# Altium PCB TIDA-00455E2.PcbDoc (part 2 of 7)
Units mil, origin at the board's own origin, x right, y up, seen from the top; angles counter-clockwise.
Board outline 6693 x 6693.1 mil, 8 copper layers (Layer 1 - Top Layer, Layer 2 - GND, Layer 3 - Sensitive, Layer 4 - GND, Layer 5 - PWR, Layer 6 - Signal, Layer 7 - GND, Layer 8 - Bottom Layer), stack 63.122 mil thick; 537 components, 407 nets, 1686 pads, 1249 vias.
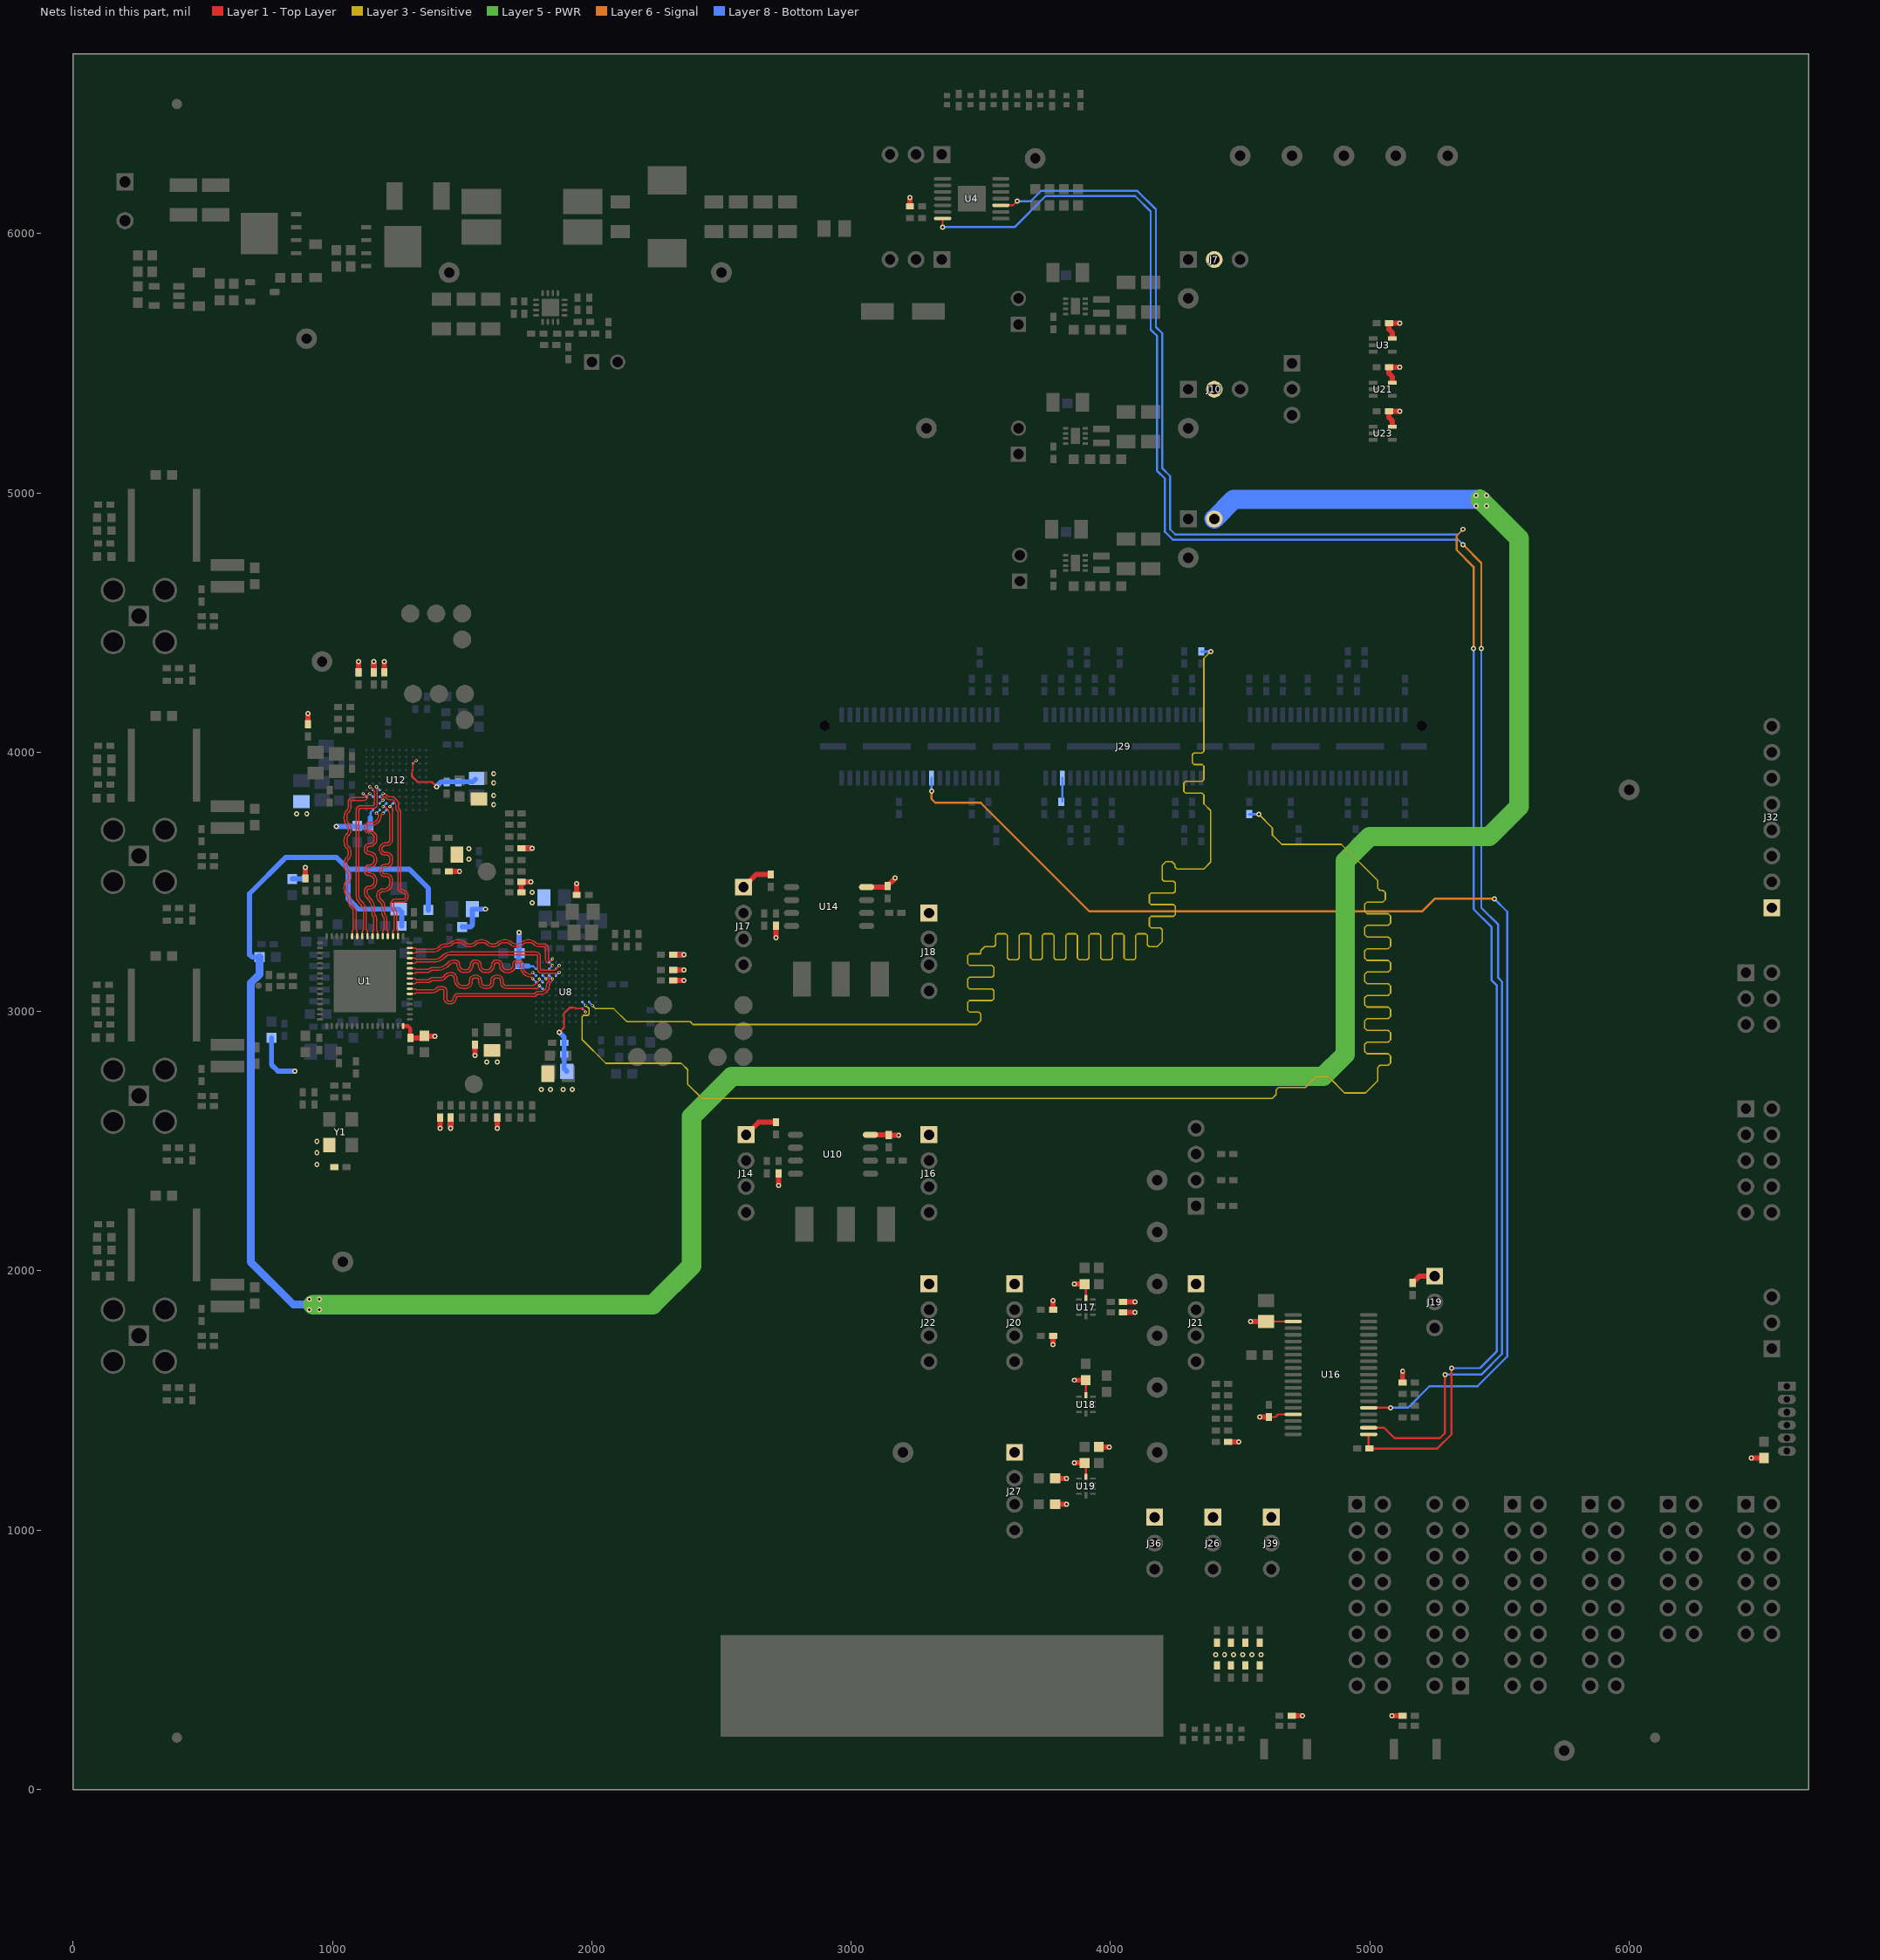
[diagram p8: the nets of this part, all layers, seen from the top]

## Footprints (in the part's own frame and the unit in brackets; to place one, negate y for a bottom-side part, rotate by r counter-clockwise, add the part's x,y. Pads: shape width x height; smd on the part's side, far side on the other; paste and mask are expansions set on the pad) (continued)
Samtec_QTE-060-01-x-D-A [mm] "Header, 0.8mm, 60x2, SMT"
  rect 0.46x1.45 smd: 1(-27.595,3.09) 2(-27.595,-3.08) 3(-26.795,3.09) 4(-26.795,-3.08) 5(-25.995,3.09) 6(-25.995,-3.08) 7(-25.195,3.09) 8(-25.195,-3.08) 9(-24.395,3.09) 10(-24.395,-3.08) 11(-23.595,3.09) 12(-23.595,-3.08) 13(-22.795,3.09) 14(-22.795,-3.08) 15(-21.995,3.09) 16(-21.995,-3.08) 17(-21.195,3.09) 18(-21.195,-3.08) 19(-20.395,3.09) 20(-20.395,-3.08) 21(-19.595,3.09) 22(-19.595,-3.08) 23(-18.795,3.09) 24(-18.795,-3.08) 25(-17.995,3.09) 26(-17.995,-3.08) 27(-17.195,3.09) 28(-17.195,-3.08) 29(-16.395,3.09) 30(-16.395,-3.08) 31(-15.595,3.09) 32(-15.595,-3.08) 33(-14.795,3.09) 34(-14.795,-3.08) 35(-13.995,3.09) 36(-13.995,-3.08) 37(-13.195,3.09) 38(-13.195,-3.08) 39(-12.395,3.09) 40(-12.395,-3.08) 41(-7.595,3.09) 42(-7.595,-3.08) 43(-6.795,3.09) 44(-6.795,-3.08) 45(-5.995,3.09) 46(-5.995,-3.08) 47(-5.195,3.09) 48(-5.195,-3.08) 49(-4.395,3.09) 50(-4.395,-3.08) 51(-3.595,3.09) 52(-3.595,-3.08) 53(-2.795,3.09) 54(-2.795,-3.08) 55(-1.995,3.09) 56(-1.995,-3.08) 57(-1.195,3.09) 58(-1.195,-3.08) 59(-0.395,3.09) 60(-0.395,-3.08) 61(0.405,3.09) 62(0.405,-3.08) 63(1.205,3.09) 64(1.205,-3.08) 65(2.005,3.09) 66(2.005,-3.08) 67(2.805,3.09) 68(2.805,-3.08) 69(3.605,3.09) 70(3.605,-3.08) 71(4.405,3.09) 72(4.405,-3.08) 73(5.205,3.09) 74(5.205,-3.08) 75(6.005,3.09) 76(6.005,-3.08) 77(6.805,3.09) 78(6.805,-3.08) 79(7.605,3.09) 80(7.605,-3.08) 81(12.405,3.09) 82(12.405,-3.08) 83(13.205,3.09) 84(13.205,-3.08) 85(14.005,3.09) 86(14.005,-3.08) 87(14.805,3.09) 88(14.805,-3.08) 89(15.605,3.09) 90(15.605,-3.08) 91(16.405,3.09) 92(16.405,-3.08) 93(17.205,3.09) 94(17.205,-3.08) 95(18.005,3.09) 96(18.005,-3.08) 97(18.805,3.09) 98(18.805,-3.08) 99(19.605,3.09) 100(19.605,-3.08) 101(20.405,3.09) 102(20.405,-3.08) 103(21.205,3.09) 104(21.205,-3.08) 105(22.005,3.09) 106(22.005,-3.08) 107(22.805,3.09) 108(22.805,-3.08) 109(23.605,3.09) 110(23.605,-3.08) 111(24.405,3.09) 112(24.405,-3.08) 113(25.205,3.09) 114(25.205,-3.08) 115(26.005,3.09) 116(26.005,-3.08) 117(26.805,3.09) 118(26.805,-3.08) 119(27.605,3.09) 120(27.605,-3.08)
  round 1.02 hole 1.02 unplated mask+0: MH1(-29.24,2.04) MH2(29.24,2.04)
  rect 2.54x0.64 smd: MP1(-28.445,0) MP4(-11.555,0) MP5(-8.445,0) MP8(8.445,0) MP9(11.555,0) MP12(28.445,0)
  rect 4.7x0.64 smd: MP2(-23.175,0) MP3(-16.825,0) MP6(-3.175,0) MP7(3.175,0) MP10(16.825,0) MP11(23.175,0)
  silkscreen extent -30,-2.98 30.01,3.25, body extent -30,-3.56 30.01,3.56, height 4.34
SM_RADIAL_D [mm] "6.3 x 5.8mm:  Panasonic D"
  rect 3.2x1.6 smd: 1(-2.5,0) 2(2.5,0)
  silkscreen extent -3.4,-3.4 3.4,3.4, body extent -3.41,-3.41 3.41,3.41, height 6.1
SMC [mil] "Molded Diode, 2-Leads, Body 6.9x5.8mm, IPC Medium Density, based on OnSemi component dimensions and land patterns"
  rect 110x150 smd: 1(-140.49,0) 2(140.49,0)
  silkscreen extent -221,-124 189,123, body extent -156,-116 156,116, height 91
SML-P1_GREEN [mm] "ROHM"
  rect 0.5x0.6 smd: 1(-0.45,0) 2(0.45,0)
  silkscreen extent -0.95,-0.3 -0.95,0.3, body extent -0.53,-0.33 0.53,0.33, height 0.25
SML-P1_RED [mm] "ROHM"
  rect 0.5x0.6 smd: 1(-0.45,0) 2(0.45,0)
  silkscreen extent -0.95,-0.3 -0.95,0.3, body extent -0.52,-0.33 0.52,0.33, height 0.25
SML-P1_YELLOW-GREEN [mm] "Rohm Semiconductor"
  rect 0.5x0.6 smd: 1(-0.45,0) 2(0.45,0)
  silkscreen extent -0.63,-0.61 1.33,0.61, body extent -0.55,-0.35 0.55,0.35, height 0.25
SOD-123 [mm] "On Semi recommended land pattern"
  rect 0.915x1.22 smd: 1(-1.637,0) 2(1.637,0)
  silkscreen extent -2.74,-1.17 2.03,1.17, body extent -1.93,-0.9 1.93,0.9, height 1.35
SOIC127P800X216-8N [mm] "SOIC, 8-Leads, Body 5.3x5.3mm (max), Pitch 1.27mm, IPC Medium Density"
  oval 1.5x0.6 smd: 1(-3.675,1.905) 2(-3.675,0.635) 3(-3.675,-0.635) 4(-3.675,-1.905) 5(3.675,-1.905) 6(3.675,-0.635) 7(3.675,0.635) 8(3.675,1.905)
  silkscreen extent -4.11,-2.7 2.69,2.7, body extent -4.1,-2.7 4.1,2.7, height 2.17
SOT-23 [mm] "SOT23, 3-Leads, Body 2.9x1.3mm, Pitch 0.95mm, Lead Span 2.5mm, IPC Medium Density"
  rrect50% 1x0.6 smd: 1(-1.2,0.95) 2(-1.2,-0.95) 3(1.2,0)
  silkscreen extent -1.63,-1.5 0.7,1.5, body extent -1.16,-1.45 1.21,1.45, height 1
SW_SKRKAEE010 [mm] "Alps recommended land pattern"
  rect 0.8x2 smd: 1(-2.1,0) 2(2.1,0)
  body extent -2.4,-1.45 2.4,1.45, height 1.96
Testpoint_Keystone_Miniature [mil] "Miniature SMT test point"
  rect 135x70 smd: 1(0,0)
  silkscreen extent -78,-46 78,45, body extent -52,-20 52,20, height 61
TI_Stacked_SolderMask_Medium [mil]
  rect 1706x392 smd paste-196 mask-196: 0(0,0)
TP_25MIL-SMT [mil]
  round 25 smd mask-2.5: 1(0,0)
TSW-102-07-G-S [mm] "Samtec 100mil, 1x2, 230 mil above insulator"
  rect 1.65x1.65 hole 1.016 mask+0: 1(-1.27,0)
  round 1.65 hole 1.016 mask+0: 2(1.27,0)
  silkscreen extent -3.56,-1.27 2.54,1.27, body extent -2.54,-1.27 2.54,1.27, height 8.38
TSW-103-07-G-D [mm] "Samtec 100mil, 2x3, 230 mil above insulator"
  rect 1.65x1.65 hole 1.016: 1(-2.54,-1.27)
  round 1.65 hole 1.016: 2(-2.54,1.27) 3(0,-1.27) 4(0,1.27) 5(2.54,-1.27) 6(2.54,1.27)
  silkscreen extent -4.83,-2.54 3.81,2.54, body extent -3.81,-2.54 3.81,2.54, height 8.38
TSW-103-07-G-S [mm] "Samtec 100mil, 1x3, 230 mil above insulator"
  rect 1.65x1.65 hole 1.016: 1(-2.54,0)
  round 1.65 hole 1.016: 2(0,0) 3(2.54,0)
  silkscreen extent -4.84,-1.27 3.81,1.27, body extent -3.81,-1.27 3.81,1.27, height 8.38
TSW-104-07-G-S [mm] "Samtec 100mil, 1x4, 230 mil above insulator"
  rect 1.65x1.65 hole 1.016 mask+0: 1(-3.81,0)
  round 1.65 hole 1.016 mask+0: 2(-1.27,0) 3(1.27,0) 4(3.81,0)
  silkscreen extent -6.1,-1.27 5.08,1.27, body extent -5.08,-1.27 5.08,1.27, height 8.38
TSW-105-07-G-D [mm] "Samtec 100mil, 2x5, 230 mil above insulator"
  rect 1.65x1.65 hole 1.016 mask+0: 1(-5.08,-1.27)
  round 1.65 hole 1.016 mask+0: 2(-5.08,1.27) 3(-2.54,-1.27) 4(-2.54,1.27) 5(0,-1.27) 6(0,1.27) 7(2.54,-1.27) 8(2.54,1.27) 9(5.08,-1.27) 10(5.08,1.27)
  silkscreen extent -7.37,-2.54 6.35,2.54, body extent -6.35,-2.54 6.35,2.54, height 8.38
TSW-106-07-G-D [mm] "Samtec 100mil, 2x6, 230 mil above insulator"
  rect 1.65x1.65 hole 1.016 mask+0: 1(-6.35,-1.27)
  round 1.65 hole 1.016 mask+0: 2(-6.35,1.27) 3(-3.81,-1.27) 4(-3.81,1.27) 5(-1.27,-1.27) 6(-1.27,1.27) 7(1.27,-1.27) 8(1.27,1.27) 9(3.81,-1.27) 10(3.81,1.27) 11(6.35,-1.27) 12(6.35,1.27)
  silkscreen extent -8.64,-2.54 7.62,2.54, body extent -7.62,-2.54 7.62,2.54, height 8.38
TSW-108-07-G-D [mm] "Samtec 100mil, 2x8, 230 mil above insulator"
  rect 1.65x1.65 hole 1.016 mask+0: 1(-8.89,-1.27)
  round 1.65 hole 1.016 mask+0: 2(-8.89,1.27) 3(-6.35,-1.27) 4(-6.35,1.27) 5(-3.81,-1.27) 6(-3.81,1.27) 7(-1.27,-1.27) 8(-1.27,1.27) 9(1.27,-1.27) 10(1.27,1.27) 11(3.81,-1.27) 12(3.81,1.27) 13(6.35,-1.27) 14(6.35,1.27) 15(8.89,-1.27) 16(8.89,1.27)
  silkscreen extent -11.18,-2.54 10.16,2.54, body extent -10.16,-2.54 10.16,2.54, height 8.38
TSW-108-07-G-S [mm] "Samtec 100mil, 1x8, 230 mil above insulator"
  rect 1.65x1.65 hole 1.016 mask+0: 1(-8.89,0)
  round 1.65 hole 1.016 mask+0: 2(-6.35,0) 3(-3.81,0) 4(-1.27,0) 5(1.27,0) 6(3.81,0) 7(6.35,0) 8(8.89,0)
  silkscreen extent -11.18,-1.27 10.16,1.27, body extent -10.16,-1.27 10.16,1.27, height 8.38
TXC_7C [mm] "TXC"
  rect 1.2x1.4 smd: 1(-1.1,1.27) 2(-1.1,-1.27) 3(1.1,-1.27) 4(1.1,1.27)
  silkscreen extent -2.32,-2.63 1.73,2.63, body extent -1.7,-2.6 1.7,2.6, height 1.4
VLS201610ET [mm] "TDK"
  rect 0.65x1.6 smd: 1(-0.675,0) 2(0.675,0)
  silkscreen extent -0.15,-1.02 0.15,1.02, body extent -1.05,-0.85 1.05,0.85, height 0.95
XTAL_ABM10 [mm] "ABRACON"
  rect 0.8x0.9 smd: 1(-0.625,0.825) 2(-0.625,-0.825) 3(0.625,-0.825) 4(0.625,0.825)
  silkscreen extent -1.28,-0.13 1.05,1.52, body extent -1.05,-1.3 1.05,1.3, height 0.7

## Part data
C1 C3 C5 C7 C15 C17 C19 C21 C115 C122 C124 C126 C127 C129 C130 C131 C135 C142 C144 C146 C147 C149 C150 C151 C160 C162: "CAP, CERM, 0.1 µF, 50 V, +/- 10%, X7R, 0402"
C2 C4 C6 C8 C16 C18 C20 C22: "CAP CER 4.7UF 25V 10% X5R 0603"
C9 C10 C23 C24 C78 C79: "CAP, CERM, 0.033 µF, 50 V, +/- 10%, X7R, 0402"
C11 C12 C25 C26: "CAP, CERM, 0.015 µF, 50 V, +/- 10%, X7R, 0402"
C13 C14 C27 C28: "CAP, CERM, 240 pF, 50 V, +/- 5%, C0G/NP0, 0402"
C29 C32: "CAP, CERM, 0.1uF, 50V, +10/%, X7R, 0603"
C30 C31: "Cap, Cer-X7R, 2.2uF, 100V, 10%, 1210"
C33 C34 C35 C36: "CAP, CERM, 4.7uF, 25V, +/-20%, X7R, 1206"
C37 C157: "Cap, Cer-X7R, 0.1uF, 6.3V, 10%, 0402"
C38 C39 C40: "Cap, Cer-X7R, 10uF, 25V, 10%, 1206"
C41: "Cap, Cer-X7R, 0.047uF, 6.3V, 10%, 0402"
C42: "Cap, Cer-X7R, 100pF, 50V, 10%, 0402"
C43: "Cap, Cer-X7R, 10000pF, 16V, 10%, 0402"
C44 C48 C51: "Cap, Cer-X7R, 10uF, 16V, 10%, 1206"
C45 C49 C52: "CAP, CERM, 22 µF, 16 V, +/- 10%, X5R, 1206"
C46 C50 C53: library part GRM31CR61C226KE15L, "CAP, open, 1206"
C47: "CAP, AL, 47 µF, 25 V, +/- 20%, 0.36 ohm, SMD"
C54 C60 C92: "CAP, CERM, 10 µF, 25 V, +/- 10%, X5R, 0805"
C56 C61 C69 C75 C94 C100 C106 C111 C163 C164: "CAP, CERM, 1 µF, 35 V, +/- 10%, JB, 0402"
C57 C62 C70 C76 C84 C90 C95 C101 C107 C112: library part GRM188R71C474KA88D, "CAP, CERM, 0.1uF, 50V, +/-10%, X7R, 0402"
C58 C63 C64 C65 C66 C71 C77 C85 C91 C96 C97 C102 C103 C108 C113 C114: "CAP, CERM, 0.01uF, 50V, +/-10%, C0G/NP0, 0402"
C72 C86: "CAP, CERM, 0.1uF, 50V, +/-20%, C0G/NP0, 0402"
C80 C155: library part Capacitor, "Cap, Cer-X7R, 2200pF, 50V, 10%, 0402"
C116 C119 C125 C136 C139 C145: "CAP, CERM, 10 µF, 6.3 V, +/- 20%, X7R, 0805"
C117 C137: "CAP, CERM, 2.2 µF, 10 V, +/- 20%, X5R, 0603"
C118 C120 C138 C140: "CAP, CERM, 0.47 µF, 10 V, +/- 10%, X5R, 0402"
C121 C141: "CAP, CERM, 4.7 µF, 10 V, +/- 10%, X5R, 0402"
C123 C143: "CAP, CERM, 2.2 µF, 10 V, +/- 10%, X5R, 0805"
C128 C134 C148 C154: "CAP, CERM, 18 pF, 100 V, +/- 5%, C0G/NP0, 0603"
C132 C133 C152 C153: "CAP, CERM, 1 µF, 16 V, +/- 10%, X5R, 0603"
C156: "Cap, Cer-X7R, 4.7uF, 10V, 10%, 0805"
C158 C159 C161: "CAP, CERM, 0.1uF, 16V, +/-5%, X7R, 0603"
D1 D2: "Diode, Zener, 15 V, 500 mW, SOD-123"
D3: "Diode, Schottky, 3A, 60V, SMC"
D4 D10: "LED, Yellow, SMD"
D5 D8: "LED, Orange, SMD"
D6: "LED, Red, SMD"
D7 D11 D12: "LED, Green, SMD"
D9: "LED, Yellow/green, SMD"
FID1 FID2 FID3 FID4 FID5 FID6: "Fiducial mark.  There is nothing to buy or mount."
J1 J2 J3 J4: "RIGHT ANGLE PLUG FOR PCB"
J5: "Conn Term Block, 2POS, 3.81mm, TH"
J6 J7 J8 J10 J11 J19 J26 J36 J39 J40: "Header, 100mil, 3x1, Gold, TH"
J9 J13 J15 J30: "Header, 100mil, 2x1, Tin, TH"
J12: "Header, 100mil, 2x1, Gold, TH"
J14 J16 J17 J18 J20 J21 J22 J24 J27: "Header, 100mil, 4x1, Gold, TH"
J23: "Receptacle, 50mil, 6x1, Gold, R/A, TH"
J25: "Header, 100mil, 5x2, Gold, TH"
J28 J33 J37 J38: "Header, 100mil, 8x2, Gold, TH"
J29: "Header, 0.8mm, 60x2, Gold, SMT"
J31: "Header, 100mil, 3x2, Gold, TH"
J32: "Header, 100mil, 8x1, Gold, TH"
J34 J35: "Header, 100mil, 6x2, Gold, TH"
L1 L2 L9 L10: "FERRITE CHIP 1000 OHM 400MA 0603"
L3 L5 L11 L13: "Inductor, Wirewound, Ferrite, 10 µH, 0.5 A, 0.57 ohm, SMD"
L4 L6 L12 L14: "Inductor, Shielded Drum Core, Ferrite, 100 µH, 0.7 A, 0.28 ohm, SMD"
L7 L8 L15 L16: "Ferrite Bead, 1000 ohm @ 100 MHz, 0.25 A, 0402"
L17: "Ind, Dual, 2.2uH, 20%, 6.23A, 8.05mE, Shielded, SMD"
L18 L19 L20: library part VLS201610ET-2R2M, "Inductor, Shielded, Ferrite, 2.2 µH, 1.45 A, 0.170 ohm, SMD"
L21: "Ferrite Bead, 120 ohm @ 100 MHz, 3 A, 0603"
L22 L23 L27 L28 L30: library part BLM18SG331TN1D, "1.5A Ferrite Bead, 330 ohm @ 100MHz, SMD"
L31 L32 L33 L34 L35 L36: "Ferrite Bead, 1000 ohm @ 100 MHz, 0.3 A, 0805"
Logo1: library part TI_Logo, "Texas Instrument Corporate Signature"
Logo2: library part Pb-Free
M1: "MOSFET, N/P-CH, 60 V, 4.4 A, SOT-23"
Q1 Q2: "MOSFET, P-CH, -60V, 30A, PowerPAK_SO-8L"
R1 R3 R9 R11: "RES, 2.00 k, 1%, 0.1 W, 0603"
R2 R4 R10 R12: "RES, 1.00 k, 1%, 0.1 W, 0603"
R5 R6 R13 R14: "RES, 57.6, 1%, 0.063 W, 0402"
R7 R8 R15 R16 R143 R145 R147: "RES, 200, 5%, 0.063 W, 0402"
R17: "RES, 0, 5%, 0.75 W, 2010"
R18 R22: library part Resistor, "Res, Chip, 100K, 1/10W, 1%, 0603"
R19 R20: "Res, Chip, 20K, 1/10W, 1%, 0603"
R21: library part CRCW060311R8FKEA, "RES, 11.8 ohm, 1%, 0.1W, 0603"
R23: "RES, 1.00k ohm, 1%, 0.1W, 0603"
R24 R136 R139: "Res, Chip, 0E, 1/8W, JUMP, 0805"
R25: "Res, Chip, 100K, 1/4W, 5%, 1206"
R26 R102 R104 R116 R119 R120 R141 R144 R146 R148 R149 R150: "Res, Chip, 10K, 1/16W, 5%, 0402"
R27: "RES, 2.32k ohm, 1%, 0.063W, 0402"
R28: "RES, 18.2k ohm, 1%, 0.063W, 0402"
R29: "RES, 49.9 ohm, 1%, 0.063W, 0402"
R30: "RES, 88.7 k, 1%, 0.063 W, 0402"
R31: "RES, 10.0k ohm, 1%, 0.063W, 0402"
R32 R33 R34 R35 R142 R156: "RES, 0 ohm, 5%, 0.1W, 0603"
R36 R38 R39 R41 R42 R44: "RES, 100 k, 1%, 0.1 W, 0603"
R37: "RES, 316 k, 1%, 0.1 W, 0603"
R40: "RES, 124 k, 1%, 0.1 W, 0603"
R43: "RES, 37.4 k, 1%, 0.1 W, 0603"
R45 R54: "RES, 10k ohm, 5%, 0.063W, 0402"
R46 R47 R62 R77 R80 R81 R92 R107 R110 R111: "RES, 0, 5%, 0.063 W, 0402"
R48: "RES, 13.3 k, 1%, 0.063 W, 0402"
R49: "RES, 40.2 k, 1%, 0.063 W, 0402"
R50 R64 R68 R94 R98 R125 R127: "RES, 2.2 k, 5%, 0.063 W, 0402"
R51 R159 R162: "RES, 100 ohm, 1%, 0.063W, 0402"
R52 R78 R108 R126 R128 R151 R152 R163 R164 R165 R166 R174 R175 R176 R177 R178 R179 R180 R181 R182 R186 R187 R188 R189 R190 R191 R192 R193 R194 R195 R196 R197 R198 R199 R200 R202 R203 R205 R206 R207 R208 R209 R210 R211 R212 R213 R214 R215 R216 R217 R218 R219 R220 R221 R222 R223 R224: "RES, 0 ohm, 5%, 0.063W, 0402"
R53: "RES, 56.2 k, 1%, 0.063 W, 0402"
R55: "RES, 210 k, 1%, 0.063 W, 0402"
R56 R57 R84 R85 R86 R87 R114 R115: "RES, 4.7 k, 5%, 0.063 W, 0402"
R58 R59 R60 R61 R63 R65 R66 R67 R72 R74 R75 R76 R82 R83 R88 R89 R90 R91 R93 R95 R96 R97 R105 R106 R112 R113 R129 R133 R134 R137 R138 R184 R185 R201 R204: "RES, 10 k, 5%, 0.063 W, 0402"
R69 R70 R71 R73 R99 R100 R101 R103: "RES, 33, 5%, 0.063 W, 0402"
R79 R109 R157 R158 R160 R161: "RES, 1.0 M, 5%, 0.063 W, 0402"
R117: "RES, 49.9 k, 1%, 0.063 W, 0402"
R118 R132: "RES, 220, 5%, 0.063 W, 0402"
R121 R122 R123 R124: "Res, Chip, 4.7K, 1/16W, 5%, 0402"
R130: "RES, 360, 5%, 0.063 W, 0402"
R131: "RES, 470, 5%, 0.063 W, 0402"
R135 R153 R167 R171 R172: "RES, 4.7k ohm, 5%, 0.1W, 0603"
R140 R155: "RES, 4.99 k, 1%, 0.063 W, 0402"
R154: "RES, 4.12 k, 1%, 0.063 W, 0402"
R168 R173: "RES, 487 ohm, 1%, 0.063W, 0402"
S1 S2: "Switch, Tactile, 12v, 50mA, Vertical, SMD"
TP1 TP2 TP3 TP4 TP5 TP6 TP7 TP9 TP10 TP12 TP14: "Test Point, Miniature, Red, TH"
TP8 TP11 TP13 TP15 TP43 TP44 TP45 TP46: "Test Point, Miniature, Black, TH"
TP16 TP17: "Test Point, O.025\""
TP18 TP19 TP20 TP21 TP22 TP23: "Test Point, Miniature, SMT"
TP24 TP25 TP26 TP27 TP28: "Test Point, Miniature, Yellow, TH"
TP29 TP30 TP31 TP32 TP33 TP34 TP35 TP36 TP37 TP38 TP39 TP40 TP41 TP42 TP47 TP48 TP49 TP50: library part PogoPad, "Pad for Pogo Pin Connector"
U1: "FPD-Link III Camera Hub Deserializer, RTD0064E"
U2: library part TLVH431AQDBVRQ1, "Automotive Catalog Low-Voltage Adjustable Precision Shunt Regulator, 80 mA, -40 to 125 degC, 5-pin SOT-23 (DBV), Green (RoHS & no Sb/Br)"
U3 U21 U23: "Single Bus Buffer Gate With 3-State Output, DCK0005A"
U4: "40V/100mO Single Channel Smart High Side Switch, Automotive Qualified, PWP0014C"
U5 U6 U7: "3-V to 17-V 1-A Step-Down Converter with DCS-Control™, DSG0008A"
U8 U12: "Companion ISP processor, BGA100"
U10 U14: "3V 128M-bit Serial Flash Memory With Dual SPI&QPI, SO-8"
U16: "16 MHz Mixed Signal Microcontroller with 32 KB Flash, 1024 B SARM and 32 GPIOs, -40 to 105 degC, 38-pin SOP (DA)"
U17: "IC, TS3USB221A-Q1, Dual USB Switch, UQFN-10"
U18 U19: "Automotive Catalog ESD Protected, High-Speed USB 2.0 (480-Mbps) 1:2 Multiplexer / Demultiplexer Switch, 16 ohm RON, 2.5 to 3.3V, -40 to 125 degC, 10-Pin UQFN (RSE), Green (RoHS & no Sb/Br)"
U20: "Integrated 5-A 40-V Wide Input Range Boost/SEPIC/Flyback DC-DC Regulator, RTE0016C"
Y1: "XO, 25.000MHz, 2.5V, SMD"
Y2 Y3: "Crystal, 24.576MHz, 10pF, SMD"
ZZ1 ZZ2 ZZ3: library part AssemblyNote

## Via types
v1: diameter 20, hole 10, Layer 1 - Top Layer to Layer 8 - Bottom Layer, tented both sides, 1063 vias
v2: diameter 12, hole 6, Layer 1 - Top Layer to Layer 8 - Bottom Layer, tented bottom, 140 vias
v3: diameter 19.68, hole 7.87, Layer 1 - Top Layer to Layer 8 - Bottom Layer, 38 vias
v4: diameter 19.68, hole 7.87, Layer 1 - Top Layer to Layer 8 - Bottom Layer, tented top, 4 vias
v5: diameter 15.75, hole 7.87, Layer 1 - Top Layer to Layer 8 - Bottom Layer, 4 vias

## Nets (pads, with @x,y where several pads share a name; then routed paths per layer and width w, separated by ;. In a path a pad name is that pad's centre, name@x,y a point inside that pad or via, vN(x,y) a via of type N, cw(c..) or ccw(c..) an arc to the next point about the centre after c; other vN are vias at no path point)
1V1: C92.1 J12.2 L27.1 L28.1 L30.1 | length 11569.3
  Layer 5 - PWR w75: 925,1870 2235,1870 2385,2020 2385,2595 2540,2750 4820,2750 4905,2835 4905,3580 5000,3675 5460,3675 5575,3790 5575,4825 v1(5450,4950) 5425,4975
  Layer 8 - Bottom Layer w20: L30.1@718.5,3210 690,3210 680,3220 680,3455 820,3595 1015,3595 1060.74,3549.26 ; L27.1@1266.5,3330 1266.5,3383.5 C92.1@1255,3395 1100,3395 1060.74,3434.26 1060.74,3549.26 ; L28.1@1370,3391.5 1370,3475 1295.74,3549.26 1060.74,3549.26
  Layer 8 - Bottom Layer w30: L30.1@718.5,3210 718.5,3143.5 685,3110 685,2035 850,1870 900,1870
  Layer 8 - Bottom Layer w75: J12.2@4400,4900 4475,4975 5425,4975 5440,4960
  other v1: 910,1850 950,1850 910,1890 950,1890 5410,4950 5410,4990 5450,4990
1V8: C54.1 C131.1 C132.2 C151.1 C152.2 J10.2 L21.1 L22.1 L23.1 L31.2 L34.2 R45.1 R48.2 R53.2 R136.1 R139.1 U8.K9 U12.K9 Y1.4 | length 885.2
  Layer 1 - Top Layer w20: R48.2@895,3513.62 v1(895,3555)
  Layer 8 - Bottom Layer w8: 1146.24,3747.5 1146.24,3766.91 U12.K9@1156.67,3777.34 ; 1755,3175 1774.41,3175 U8.K9@1784.84,3164.57
  Layer 8 - Bottom Layer w20: L22.1@765,2898.5 765,2795 790,2770 v1(855,2770) ; L23.1@845,3511.5 R53.2@892.87,3511.5 ; R53.2@895,3513.62 v1(895,3555) ; v1(1015,3714) C152.2@1096.24,3714 ; C152.2@1099.11,3711.12 1146.24,3711.12 1146.24,3747.5 ; L21.1@1500,3326.5 1531.5,3326.5 1540,3335 C54.1@1540,3395 v1(1590,3395) ; C132.2@1718.62,3222.13 C131.1@1718.62,3175 1755,3175 ; v1(1720,3305) 1720,3226.5 C132.2@1721.5,3225
  other v1: 940,2410 940,2455 940,2500 1805,2700 1840,2700 1770,3420 1770,3460 861.24,3762.5 901.24,3762.5 1621.24,3797.5 1621.24,3832.5
3V3: C75.1 C106.1 C107.1 C108.1 C125.1 C126.1 C127.2 C145.1 C146.1 C147.2 C156.1 C157.1 C158.1 C159.1 C161.1 C163.1 C164.1 J7.2 J14.1 J16.1 J17.1 J18.1 J19.1 J20.1 J21.1 J22.1 J26.1 J27.1 J32.1 J36.1 J39.1 L33.2 L36.2 R56.2 R57.2 R58.2 R59.2 R60.2 R61.1 R64.2 R65.2 R66.2 R67.2 R72.2 R74.2 R77.2 R78.1 R82.2 R83.2 R86.2 R87.2 R88.2 R89.2 R90.2 R91.1 R94.2 R95.2 R96.2 R97.2 R102.2 R104.2 R107.2 R108.1 R112.2 R113.2 R116.2 R119.2 R120.2 R121.2 R122.2 R123.2 R124.2 R141.2 R142.2 R144.2 R146.2 R148.2 R149.2 R150.2 R157.2 R160.2 R167.2 R171.2 R172.2 R184.2 U1.16 U3.5 U8.C3 U10.8 U12.C3 U14.8 U16.2 U16.16 U17.10 U18.10 U19.10 U21.5 U23.5 | length 4088.4
  Layer 1 - Top Layer w5: 1306.24,3917.5 1306.24,3927.5 1310.22,3931.48 1310.22,3956.48 v2(1323.01,3969.27) ; 1925,3015 1935,3015 1938.98,3011.02 1963.98,3011.02 v2(1976.77,2998.23)
  Layer 1 - Top Layer w8: 1306.24,3917.5 1306.24,3907.5 1328.24,3885.5 1383.24,3885.5 v1(1401.24,3867.5) ; v1(1875,2920) 1893,2938 1893,2993 1915,3015 1925,3015 ; C159.1@3900,1258.5 3905,1253.5 U19.10@3905,1205.43 ; C161.1@3900,1948.5 3905,1943.5 U17.10@3905,1895.43 ; U18.10@3905,1520.43 C158.1@3905,1578.5 ; C156.1@4600,1804.72 U16.2@4704.33,1804.72 ; C157.1@4610,1436.38 4636.38,1436.38 4646.46,1446.46 U16.16@4704.33,1446.46
  Layer 1 - Top Layer w15: U1.16@1276,2944.27 1290.73,2944.27 1300,2935 C108.1@1300,2898.62
  Layer 1 - Top Layer w20: R108.1@905,4108.62 v1(905,4150) ; R87.2@1100,4308.62 v1(1100,4350) ; R94.2@1160,4308.62 v1(1160,4350) ; R74.2@1200,4308.62 v1(1200,4350) ; C108.1@1300,2898.62 1347.13,2898.62 C107.1@1355,2906.5 1356.5,2905 v1(1395,2905) ; v1(1415,2550) R66.2@1415,2591.38 ; R107.2@1448.62,3540 v1(1490,3540) ; v1(1455,2550) R65.2@1455,2591.38 ; v1(1550,2831) R77.2@1550,2871.38 ; v1(1635,2550) R83.2@1635,2591.38 ; R96.2@1728.62,3460 R95.2@1728.62,3500 v1(1765,3500) ; R113.2@1728.62,3630 v1(1770,3630) ; R78.1@1941.38,3450 v1(1941.38,3493.62) ; R72.2@2313.62,3120 v1(2355,3120) ; R64.2@2313.62,3160 v1(2355,3160) ; R57.2@2313.62,3220 v1(2355,3220) ; J17.1@2585,3480 2633.62,3528.62 R89.2@2690,3528.62 ; J14.1@2595,2525 2643.62,2573.62 R59.2@2710,2573.62 ; v1(2710.51,3285) R90.2@2710.51,3331.38 ; v1(2720,2330) R60.2@2720,2376.38 ; U14.8@3059.69,3480 3136.38,3480 R91.1@3140,3483.62 3140,3485 v1(3170,3515) ; U10.8@3074.68,2525 R61.1@3143.62,2525 ; R61.1@3145,2525 R61.1@3143.62,2525 ; v1(3183.62,2523.62) R61.1@3145,2523.62 R61.1@3143.62,2525 ; R184.2@3226.38,6105 v1(3226.38,6138.62) ; v1(3778.62,1715) R122.2@3778.62,1750 ; R121.2@3778.62,1850 v1(3778.62,1885) ; R171.2@3786.5,1100 v1(3830,1100) ; R172.2@3786.5,1200 v1(3830,1200) ; v1(3860,1260) 3898.5,1260 C159.1@3900,1258.5 ; v1(3860,1578.5) C158.1@3905,1578.5 ; v1(3860,1950) 3898.5,1950 C161.1@3900,1948.5 ; R167.2@3955,1321.5 3956.5,1320 v1(3995,1320) ; R124.2@4048.62,1840 v1(4095,1840) ; R123.2@4048.62,1880 v1(4095,1880) ; R157.2@4453.62,1340 v1(4495,1340) ; v1(4540,1805) C156.1@4600,1805 ; v1(4575,1436.38) C157.1@4610,1436.38 ; R116.2@4698.62,285 v1(4740,285) ; v1(5085,285) R141.2@5126.38,285 ; U23.5@5087.4,5260 5087.4,5277.6 5073.62,5291.38 C164.1@5073.62,5315 v1(5115,5315) ; U21.5@5087.4,5430 5087.4,5447.6 5073.62,5461.38 C163.1@5073.62,5485 v1(5115,5485) ; U3.5@5087.4,5600 5087.4,5617.6 5073.62,5631.38 C75.1@5073.62,5655 v1(5115,5655) ; R160.2@5126.38,1570 v1(5126.38,1613.62) ; R102.2@5165,1953.62 5191.38,1980 J19.1@5250,1980 ; v1(6471.5,1278.5) R142.2@6520,1278.5
  Layer 8 - Bottom Layer w5: U12.C3@1310.22,3956.48 v2(1323.01,3969.27) ; U8.C3@1963.98,3011.02 v2(1976.77,2998.23)
  Layer 8 - Bottom Layer w20: R86.2@1100,4308.62 v1(1100,4350) ; R88.2@1160,4308.62 v1(1160,4350) ; C106.1@1300,2898.62 1342.13,2898.62 1348.5,2905 v1(1395,2905) ; v1(1401.24,3867.5) 1419.86,3886.12 1441.24,3886.12 1541.4,3886.12 C145.1@1551.24,3895.96 ; v1(1455,2550) R67.2@1455,2591.38 ; v1(1635,2550) R82.2@1635,2591.38 ; R97.2@1728.62,3500 v1(1765,3500) ; R112.2@1728.62,3630 v1(1770,3630) ; v1(1875,2920) 1893.62,2901.38 C126.1@1893.62,2880 C127.2@1893.62,2835 1893.62,2779.84 C125.1@1903.46,2770 ; R58.2@2313.62,3160 v1(2355,3160) ; R56.2@2313.62,3220 v1(2355,3220)
  other v1: 4405,520 4440,520 4475,520 4510,520 4545,520 4580,520 1890,2700 1925,2700 1595,2805 1635,2805 1526.24,3587.5 1526.24,3627.5 1621.24,3882.5 1621.24,3917.5
APP_BD_PORZ: J29.76 R214.1 | length 91.2
  Layer 8 - Bottom Layer w8: R214.1@3813.97,3809.66 J29.76@3813.97,3900.89
CAM_PW_CS: U4.14 U16.21 | length 7318.1
  Layer 1 - Top Layer w8: v1(3352.8,6025) U4.14@3352.8,6058.23 ; U16.21@4995.67,1395.28 5054.72,1395.28 5095,1355 5270,1355 5290,1375 v1(5290,1600)
  Layer 6 - Signal w8: v1(5360,4800) 5430,4730 v1(5430,4400)
  Layer 8 - Bottom Layer w8: v1(3352.8,6025) 3630,6025 3750,6145 4095,6145 4155,6085 4155,5630 4180,5605 4180,5085 4210,5055 4210,4850 4240,4820 5340,4820 v1(5360,4800) ; v1(5290,1600) 5430,1600 5510,1680 5510,3115 5495,3130 5495,3335 5430,3400 v1(5430,4400)
CAM_PW_SW: R185.2 U4.3 U16.20 | length 7154.7
  Layer 1 - Top Layer w8: U4.3@3577.2,6109.41 3624.41,6109.41 v1(3640,6125) ; U16.20@4995.67,1369.69 4995.67,1312.95 R185.2@4998.62,1310 ; R185.2@4998.62,1315 5260,1315 5315,1370 v1(5315,1625)
  Layer 6 - Signal w8: v1(5360,4860) 5335,4835 5335,4780 5400,4715 v1(5400,4400)
  Layer 8 - Bottom Layer w8: v1(3640,6125) 3692.5,6125 3732.5,6165 4103.28,6165 4175,6093.28 4175,5640 4200,5615 4200,5095 4230,5065 4230,4860 4250,4840 5340,4840 v1(5360,4860) ; v1(5315,1625) 5425,1625 5490,1690 5490,3100 5470,3120 5470,3325 5400,3395 v1(5400,4400)
CSI0_CLK_N: U1.22 U8.H8 | length 672.9
  Layer 1 - Top Layer w5: U1.22@1298.23,3068.29 1315.08,3068.29 ccw(c1315.08,3076.66) 1321,3070.74 cw(c1325.83,3065.91) 1325.83,3072.74 1383.23,3072.74 ccw(c1383.23,3107.77) 1408,3083 cw(c1413.37,3077.63) 1413.37,3085.22 1424.09,3085.22 cw(c1424.09,3079.31) 1430,3079.31 1430,3050 ccw(c1450,3050) 1450,3030 1456,3030 ccw(c1456,3050) 1476,3050 cw(c1484.5,3050) 1484.5,3058.5 1776.17,3058.5 ccw(c1776.17,3075.83) 1788.42,3063.58 cw(c1796.69,3055.31) 1796.69,3067 1805,3067 ccw(c1805,3098) 1836,3098 1836,3100.34 cw(c1849.66,3100.34) 1840,3110 1843.61,3113.61 ccw(c1831.04,3126.18) v2(1848.82,3126.18)
  Layer 8 - Bottom Layer w5: U8.H8@1836.02,3138.98 v2(1848.82,3126.18)
CSI0_CLK_P: U1.23 U8.J8 | length 674.7
  Layer 1 - Top Layer w5: U1.23@1298.23,3087.97 1315.08,3087.97 cw(c1315.08,3079.6) 1321,3085.52 ccw(c1325.83,3090.35) 1325.83,3083.52 1325.97,3083.38 1383.57,3083.38 ccw(c1383.57,3107.43) 1400.58,3090.42 cw(c1413.37,3077.63) 1413.37,3095.72 1424.09,3095.72 cw(c1424.09,3079.31) 1440.5,3079.31 1440.5,3050 ccw(c1450,3050) 1450,3040.5 1456,3040.5 ccw(c1456,3050) 1465.5,3050 cw(c1484.5,3050) 1484.5,3069 1776.17,3069 ccw(c1776.17,3075.83) 1781,3071 cw(c1796.69,3055.31) 1796.69,3077.5 1805,3077.5 ccw(c1805,3098) 1825.5,3098 1825.5,3102.17 cw(c1845.6,3102.17) 1831.39,3116.39 1832.46,3117.46 ccw(c1823.93,3126) 1836,3126 ccw(c1830,3126) 1830,3132 1829.05,3132 ccw(c1829.05,3126.18) v2(1823.23,3126.18)
  Layer 8 - Bottom Layer w5: U8.J8@1810.43,3138.98 v2(1823.23,3126.18)
CSI0_D0_N: U1.24 U8.J6 | length 666.2
  Layer 1 - Top Layer w5: U1.24@1298.23,3107.66 1315.08,3107.66 ccw(c1315.08,3116.03) 1321,3110.11 cw(c1325.83,3105.28) 1325.83,3112.11 1325.97,3112.25 1367,3112.25 ; 1367.05,3112.25 ccw(c1367.05,3132.58) 1381.42,3118.21 cw(c1385.76,3113.87) 1385.76,3120 1416.14,3120 ccw(c1416.14,3145.86) 1434.42,3127.58 1441.79,3134.94 cw(c1454,3122.74) 1454,3140 1459,3140 cw(c1459,3130) 1469,3130 1469,3125.5 ccw(c1505,3125.5) 1505,3089.5 1515,3089.5 ccw(c1515,3113) 1538.5,3113 1538.5,3118.5 cw(c1550,3118.5) 1550,3130 1553,3130 cw(c1553,3118.5) 1564.5,3118.5 1564.5,3113 ccw(c1588,3113) 1588,3089.5 1598,3089.5 ccw(c1598,3113) 1621.5,3113 1621.5,3118.5 cw(c1633,3118.5) 1633,3130 1636,3130 cw(c1636,3118.5) 1647.5,3118.5 1647.5,3113 ccw(c1671,3113) 1671,3089.5 1786.55,3089.5 ccw(c1786.55,3100.59) v2(1797.64,3100.59)
  Layer 8 - Bottom Layer w5: v2(1797.64,3100.59) U8.J6@1810.43,3087.8
CSI0_D0_P: U1.25 U8.J7 | length 672.6
  Layer 1 - Top Layer w5: U1.25@1298.23,3127.34 1315.08,3127.34 cw(c1315.08,3118.97) 1321,3124.89 ccw(c1325.83,3129.72) 1325.83,3122.89 1325.97,3122.75 1367.05,3122.75 ccw(c1367.05,3132.58) 1374,3125.63 cw(c1385.76,3113.87) 1385.76,3130.5 1416.14,3130.5 ccw(c1416.14,3145.86) 1427,3135 1434.37,3142.37 cw(c1454,3122.74) 1454,3150.5 1459,3150.5 cw(c1459,3130) 1479.5,3130 1479.5,3125.5 ccw(c1505,3125.5) 1505,3100 1515,3100 ccw(c1515,3113) 1528,3113 1528,3118.5 cw(c1550,3118.5) 1550,3140.5 1553,3140.5 cw(c1553,3118.5) 1575,3118.5 1575,3113 ccw(c1588,3113) 1588,3100 1598,3100 ccw(c1598,3113) 1611,3113 1611,3118.5 cw(c1633,3118.5) 1633,3140.5 1636,3140.5 cw(c1636,3118.5) 1658,3118.5 1658,3113 ccw(c1671,3113) 1671,3100 1765.27,3100 ccw(c1765.27,3130.73) 1787,3109 1793.01,3115.01 ccw(c1781.84,3126.18) v2(1797.64,3126.18)
  Layer 8 - Bottom Layer w5: v2(1797.64,3126.18) U8.J7@1810.43,3113.39
CSI0_D1_N: U1.26 U8.K7 | length 673.1
  Layer 1 - Top Layer w5: U1.26@1298.23,3147.03 1315.08,3147.03 ccw(c1315.08,3155.4) 1321,3149.48 cw(c1325.83,3144.65) 1325.83,3151.48 1325.97,3151.62 1367.05,3151.62 ccw(c1367.05,3171.95) 1381.42,3157.58 cw(c1385.76,3153.24) 1385.76,3159.37 1405,3159.37 ccw(c1405,3220.25) 1448.05,3177.2 1451.42,3180.58 cw(c1469.35,3162.65) 1469.35,3188 1472,3188 cw(c1472,3180) 1480,3180 1480,3179.5 ccw(c1509,3179.5) 1509,3150.5 1513,3150.5 ccw(c1513,3179.5) 1542,3179.5 1542,3180 cw(c1550,3180) 1550,3188 1554,3188 cw(c1554,3180) 1562,3180 1562,3179.5 ccw(c1591,3179.5) 1591,3150.5 1595,3150.5 ccw(c1595,3179.5) 1624,3179.5 1624,3180 cw(c1632,3180) 1632,3188 1636,3188 cw(c1636,3180) 1644,3180 1644,3179 ccw(c1673,3179) 1673,3150 1677,3150 ccw(c1677,3179) 1706,3179 1706,3180 cw(c1714,3180) 1714,3188 1718,3188 cw(c1718,3180) 1726,3180 1726,3171.25 ccw(c1763.8,3171.25) 1763.8,3133.44 1764.79,3133.44 cw(c1764.79,3126.18) v2(1772.05,3126.18)
  Layer 8 - Bottom Layer w5: v2(1772.05,3126.18) U8.K7@1784.84,3113.39
CSI0_D1_P: U1.27 U8.K8 | length 673.2
  Layer 1 - Top Layer w5: U1.27@1298.23,3166.71 1315.08,3166.71 cw(c1315.08,3158.34) 1321,3164.26 ccw(c1325.83,3169.09) 1325.83,3162.26 1325.97,3162.12 1367.05,3162.12 ccw(c1367.05,3171.95) 1374,3165 cw(c1385.76,3153.24) 1385.76,3169.87 1405,3169.87 ccw(c1405,3220.25) 1440.63,3184.63 1444,3188 cw(c1469.35,3162.65) 1469.35,3198.5 1472,3198.5 cw(c1472,3180) 1490.5,3180 1490.5,3179.5 ccw(c1509,3179.5) 1509,3161 1513,3161 ccw(c1513,3179.5) 1531.5,3179.5 1531.5,3180 cw(c1550,3180) 1550,3198.5 1554,3198.5 cw(c1554,3180) 1572.5,3180 1572.5,3179.5 ccw(c1591,3179.5) 1591,3161 1595,3161 ccw(c1595,3179.5) 1613.5,3179.5 1613.5,3180 cw(c1632,3180) 1632,3198.5 1636,3198.5 cw(c1636,3180) 1654.5,3180 1654.5,3179 ccw(c1673,3179) 1673,3160.5 1677,3160.5 ccw(c1677,3179) 1695.5,3179 1695.5,3180 cw(c1714,3180) 1714,3198.5 1718,3198.5 cw(c1718,3180) 1736.5,3180 1736.5,3170.44 ccw(c1762.43,3170.44) 1762.43,3144.51 1764.79,3144.51 ccw(c1764.79,3151.77) v2(1772.05,3151.77)
  Layer 8 - Bottom Layer w5: v2(1772.05,3151.77) U8.K8@1784.84,3138.98
CSI0_D2_N: U1.28 U8.G8 | length 665.2
  Layer 1 - Top Layer w5: U1.28@1298.23,3186.4 1315.08,3186.4 ccw(c1315.08,3194.77) 1321,3188.85 cw(c1325.83,3184.02) 1325.83,3190.85 1393.55,3190.85 ccw(c1393.55,3240.45) 1428.62,3205.38 1433.93,3210.69 cw(c1454,3190.62) 1454,3219 1784.17,3219 cw(c1784.17,3212.17) 1791,3212.17 1791,3164.71 ccw(c1807.21,3164.71) 1807.21,3148.5 1866.53,3148.5 ccw(c1866.53,3159.63) v2(1874.41,3151.77)
  Layer 8 - Bottom Layer w5: U8.G8@1861.61,3138.98 v2(1874.41,3151.77)
CSI0_D2_P: U1.29 U8.G9 | length 671.9
  Layer 1 - Top Layer w5: U1.29@1298.23,3206.08 1315.08,3206.08 cw(c1315.08,3197.71) 1321,3203.63 ccw(c1325.83,3208.46) 1325.83,3201.63 1393.55,3201.63 ccw(c1393.55,3240.45) 1421,3213 1425.83,3217.83 cw(c1454,3189.67) 1454,3229.5 1784.17,3229.5 cw(c1784.17,3212.17) 1801.5,3212.17 1801.5,3164.71 ccw(c1807.21,3164.71) 1807.21,3159 1849.83,3159 ccw(c1849.83,3178.73) 1863.78,3164.78 1873.03,3174.03 ccw(c1869.7,3177.36) v2(1874.41,3177.36)
  Layer 8 - Bottom Layer w5: U8.G9@1861.61,3164.57 v2(1874.41,3177.36)
CSI0_D3_N: U1.30 U8.H9 | length 668.9
  Layer 1 - Top Layer w5: U1.30@1298.23,3225.77 1315.08,3225.77 ccw(c1315.08,3234.14) 1321,3228.22 cw(c1325.83,3223.39) 1325.83,3230.22 1390,3230.22 ccw(c1390,3266.6) 1415.73,3240.88 1418.42,3243.58 cw(c1433.93,3228.06) 1433.93,3250 1441.72,3250 ccw(c1441.72,3279.28) 1462.42,3258.58 cw(c1480.35,3240.65) 1480.35,3266 1487,3266 cw(c1487,3240.65) 1504.92,3258.58 ccw(c1525.63,3279.28) 1525.63,3250 1532.28,3250 ccw(c1532.28,3279.28) 1552.98,3258.58 cw(c1570.91,3240.65) 1570.91,3266 1577.56,3266 cw(c1577.56,3240.65) 1595.48,3258.58 ccw(c1616.18,3279.28) 1616.18,3250 1622.83,3250 ccw(c1622.83,3279.28) 1643.54,3258.58 cw(c1661.46,3240.65) 1661.46,3266 1668.11,3266 cw(c1668.11,3240.65) 1686.04,3258.58 ccw(c1706.74,3279.28) 1706.74,3250 1713.39,3250 ccw(c1713.39,3279.28) 1734.09,3258.58 cw(c1752.02,3240.65) 1752.02,3266 1758.67,3266 cw(c1758.67,3240.65) 1776.59,3258.58 ccw(c1797.3,3279.28) 1797.3,3250 1815.25,3250 cw(c1815.25,3243.37) 1821.89,3243.37 1821.89,3202.2 ccw(c1839.47,3202.2) 1839.47,3184.62 1841.56,3184.62 cw(c1841.56,3177.36) v2(1848.82,3177.36)
  Layer 8 - Bottom Layer w5: U8.H9@1836.02,3164.57 v2(1848.82,3177.36)
CSI0_D3_P: U1.31 U8.H10 | length 668.4
  Layer 1 - Top Layer w5: U1.31@1298.23,3245.45 1315.08,3245.45 cw(c1315.08,3237.08) 1321,3243 ccw(c1325.83,3247.83) 1325.83,3241 1390,3241 ccw(c1390,3267.56) 1408.78,3248.78 1411,3251 cw(c1433.93,3228.06) 1433.93,3260.5 1441.72,3260.5 ccw(c1441.72,3279.28) 1455,3266 cw(c1480.35,3240.65) 1480.35,3276.5 1487,3276.5 cw(c1487,3240.65) 1512.35,3266 ccw(c1525.63,3279.28) 1525.63,3260.5 1532.28,3260.5 ccw(c1532.28,3279.28) 1545.56,3266 cw(c1570.91,3240.65) 1570.91,3276.5 1577.56,3276.5 cw(c1577.56,3240.65) 1602.91,3266 ccw(c1616.18,3279.28) 1616.18,3260.5 1622.83,3260.5 ccw(c1622.83,3279.28) 1636.11,3266 cw(c1661.46,3240.65) 1661.46,3276.5 1668.11,3276.5 cw(c1668.11,3240.65) 1693.46,3266 ccw(c1706.74,3279.28) 1706.74,3260.5 1713.39,3260.5 ccw(c1713.39,3279.28) 1726.67,3266 cw(c1752.02,3240.65) 1752.02,3276.5 1758.67,3276.5 cw(c1758.67,3240.65) 1784.02,3266 ccw(c1797.3,3279.28) 1797.3,3260.5 1815.25,3260.5 cw(c1815.25,3243.37) 1832.39,3243.37 1832.39,3202.2 ccw(c1838.9,3202.2) 1838.9,3195.69 1841.56,3195.69 ccw(c1841.56,3202.95) v2(1848.82,3202.95)
  Layer 8 - Bottom Layer w5: U8.H10@1836.02,3190.16 v2(1848.82,3202.95)
CSI1_CLK_N: U1.34 U12.H8 | length 672.9
  Layer 1 - Top Layer w5: v2(1195.06,3841.32) cw(c1195.06,3823.54) 1207.63,3836.11 1211.24,3832.5 ccw(c1220.9,3842.16) 1220.9,3828.5 1223.24,3828.5 cw(c1223.24,3797.5) 1254.24,3797.5 1254.24,3789.19 ccw(c1265.93,3789.19) 1257.66,3780.92 cw(c1245.41,3768.67) 1262.74,3768.67 1262.74,3477 ccw(c1271.24,3477) 1271.24,3468.5 cw(c1271.24,3448.5) 1291.24,3448.5 1291.24,3442.5 cw(c1271.24,3442.5) 1271.24,3422.5 1241.93,3422.5 ccw(c1241.93,3416.59) 1236.02,3416.59 1236.02,3405.87 ccw(c1243.61,3405.87) 1238.24,3400.5 cw(c1213.47,3375.73) 1248.5,3375.73 1248.5,3318.33 ccw(c1255.33,3318.33) 1250.5,3313.5 cw(c1244.58,3307.58) 1252.95,3307.58 U1.34@1252.95,3290.73
  Layer 8 - Bottom Layer w5: U12.H8@1182.26,3828.52 v2(1195.06,3841.32)
CSI1_CLK_P: U1.35 U12.J8 | length 674.7
  Layer 1 - Top Layer w5: v2(1195.06,3815.73) cw(c1195.06,3821.55) 1189.24,3821.55 1189.24,3822.5 cw(c1195.24,3822.5) 1195.24,3828.5 cw(c1195.24,3816.43) 1203.78,3824.96 1204.85,3823.89 ccw(c1219.07,3838.1) 1219.07,3818 1223.24,3818 cw(c1223.24,3797.5) 1243.74,3797.5 1243.74,3789.19 ccw(c1265.93,3789.19) 1250.24,3773.5 cw(c1245.41,3768.67) 1252.24,3768.67 1252.24,3477 ccw(c1271.24,3477) 1271.24,3458 cw(c1271.24,3448.5) 1280.74,3448.5 1280.74,3442.5 cw(c1271.24,3442.5) 1271.24,3433 1241.93,3433 ccw(c1241.93,3416.59) 1225.52,3416.59 1225.52,3405.87 ccw(c1243.61,3405.87) 1230.82,3393.08 cw(c1213.81,3376.07) 1237.86,3376.07 1237.86,3318.47 1237.72,3318.33 cw(c1230.89,3318.33) 1235.72,3313.5 ccw(c1241.64,3307.58) 1233.27,3307.58 U1.35@1233.27,3290.73
  Layer 8 - Bottom Layer w5: U12.J8@1182.26,3802.93 v2(1195.06,3815.73)
CSI1_D0_N: U1.36 U12.J6 | length 666.2
  Layer 1 - Top Layer w5: 1208.99,3359.5 1208.99,3318.47 1209.13,3318.33 ccw(c1215.96,3318.33) 1211.13,3313.5 cw(c1205.21,3307.58) 1213.58,3307.58 U1.36@1213.58,3290.73 ; 1208.99,3359.55 ccw(c1188.66,3359.55) 1203.03,3373.92 cw(c1207.37,3378.26) 1201.24,3378.26 1201.24,3408.64 ccw(c1175.38,3408.64) 1193.66,3426.92 1186.3,3434.29 cw(c1198.5,3446.5) 1181.24,3446.5 1181.24,3451.5 cw(c1191.24,3451.5) 1191.24,3461.5 1195.74,3461.5 ccw(c1195.74,3497.5) 1231.74,3497.5 1231.74,3507.5 ccw(c1208.24,3507.5) 1208.24,3531 1202.74,3531 cw(c1202.74,3542.5) 1191.24,3542.5 1191.24,3545.5 cw(c1202.74,3545.5) 1202.74,3557 1208.24,3557 ccw(c1208.24,3580.5) 1231.74,3580.5 1231.74,3590.5 ccw(c1208.24,3590.5) 1208.24,3614 1202.74,3614 cw(c1202.74,3625.5) 1191.24,3625.5 1191.24,3628.5 cw(c1202.74,3628.5) 1202.74,3640 1208.24,3640 ccw(c1208.24,3663.5) 1231.74,3663.5 1231.74,3779.05 ccw(c1220.65,3779.05) v2(1220.65,3790.14)
  Layer 8 - Bottom Layer w5: v2(1220.65,3790.14) U12.J6@1233.44,3802.93
CSI1_D0_P: U1.37 U12.J7 | length 672.6
  Layer 1 - Top Layer w5: U1.37@1193.9,3290.73 1193.9,3307.58 cw(c1202.27,3307.58) 1196.35,3313.5 ccw(c1191.52,3318.33) 1198.35,3318.33 1198.49,3318.47 1198.49,3359.55 ccw(c1188.66,3359.55) 1195.61,3366.5 cw(c1207.37,3378.26) 1190.74,3378.26 1190.74,3408.64 ccw(c1175.38,3408.64) 1186.24,3419.5 1178.87,3426.87 cw(c1198.5,3446.5) 1170.74,3446.5 1170.74,3451.5 cw(c1191.24,3451.5) 1191.24,3472 1195.74,3472 ccw(c1195.74,3497.5) 1221.24,3497.5 1221.24,3507.5 ccw(c1208.24,3507.5) 1208.24,3520.5 1202.74,3520.5 cw(c1202.74,3542.5) 1180.74,3542.5 1180.74,3545.5 cw(c1202.74,3545.5) 1202.74,3567.5 1208.24,3567.5 ccw(c1208.24,3580.5) 1221.24,3580.5 1221.24,3590.5 ccw(c1208.24,3590.5) 1208.24,3603.5 1202.74,3603.5 cw(c1202.74,3625.5) 1180.74,3625.5 1180.74,3628.5 cw(c1202.74,3628.5) 1202.74,3650.5 1208.24,3650.5 ccw(c1208.24,3663.5) 1221.24,3663.5 1221.24,3757.77 ccw(c1190.51,3757.77) 1212.24,3779.5 1206.23,3785.51 ccw(c1195.06,3774.34) v2(1195.06,3790.14)
  Layer 8 - Bottom Layer w5: v2(1195.06,3790.14) U12.J7@1207.85,3802.93
CSI1_D1_N: U1.38 U12.K7 | length 672.2
  Layer 1 - Top Layer w5: U1.38@1174.21,3290.73 1174.21,3307.58 ccw(c1165.84,3307.58) 1171.76,3313.5 cw(c1176.59,3318.33) 1169.76,3318.33 1169.62,3318.47 1169.62,3359.55 ccw(c1149.29,3359.55) 1163.66,3373.92 cw(c1168,3378.26) 1161.87,3378.26 1161.87,3397.5 ccw(c1100.99,3397.5) 1144.04,3440.55 1140.66,3443.92 cw(c1158.59,3461.85) 1133.24,3461.85 1133.24,3464.5 cw(c1141.24,3464.5) 1141.24,3472.5 1141.74,3472.5 ccw(c1141.74,3501.5) 1170.74,3501.5 1170.74,3505.5 ccw(c1141.74,3505.5) 1141.74,3534.5 1141.24,3534.5 cw(c1141.24,3542.5) 1133.24,3542.5 1133.24,3546.5 cw(c1141.24,3546.5) 1141.24,3554.5 1141.74,3554.5 ccw(c1141.74,3583.5) 1170.74,3583.5 1170.74,3587.5 ccw(c1141.74,3587.5) 1141.74,3616.5 1141.24,3616.5 cw(c1141.24,3624.5) 1133.24,3624.5 1133.24,3628.5 cw(c1141.24,3628.5) 1141.24,3636.5 1142.24,3636.5 ccw(c1142.24,3665.5) 1171.24,3665.5 1171.24,3669.5 ccw(c1142.24,3669.5) 1142.24,3698.5 1141.24,3698.5 cw(c1141.24,3706.5) 1133.24,3706.5 1133.24,3710.5 cw(c1141.24,3710.5) 1141.24,3718.5 1149.99,3718.5 ccw(c1149.99,3756.3) 1187.8,3756.3 ; 1187.8,3757.29 cw(c1195.06,3757.29) v2(1195.06,3764.55)
  Layer 8 - Bottom Layer w5: v2(1195.06,3764.55) U12.K7@1207.85,3777.34
CSI1_D1_P: U1.39 U12.K8 | length 670.8
  Layer 1 - Top Layer w5: U1.39@1154.53,3290.73 1154.53,3307.58 cw(c1162.9,3307.58) 1156.98,3313.5 ccw(c1152.15,3318.33) 1158.98,3318.33 1159.12,3318.47 1159.12,3359.55 ccw(c1149.29,3359.55) 1156.24,3366.5 cw(c1168,3378.26) 1151.37,3378.26 1151.37,3397.5 ccw(c1100.99,3397.5) 1136.61,3433.13 1133.24,3436.5 cw(c1158.59,3461.85) 1122.74,3461.85 1122.74,3464.5 cw(c1141.24,3464.5) 1141.24,3483 1141.74,3483 ccw(c1141.74,3501.5) 1160.24,3501.5 1160.24,3505.5 ccw(c1141.74,3505.5) 1141.74,3524 1141.24,3524 cw(c1141.24,3542.5) 1122.74,3542.5 1122.74,3546.5 cw(c1141.24,3546.5) 1141.24,3565 1141.74,3565 ccw(c1141.74,3583.5) 1160.24,3583.5 1160.24,3587.5 ccw(c1141.74,3587.5) 1141.74,3606 1141.24,3606 cw(c1141.24,3624.5) 1122.74,3624.5 1122.74,3628.5 cw(c1141.24,3628.5) 1141.24,3647 1142.24,3647 ccw(c1142.24,3665.5) 1160.74,3665.5 1160.74,3669.5 ccw(c1142.24,3669.5) 1142.24,3688 1141.24,3688 cw(c1141.24,3706.5) 1122.74,3706.5 1122.74,3710.5 cw(c1141.24,3710.5) 1141.24,3729 1150.8,3729 ccw(c1150.8,3754.93) 1176.73,3754.93 ; v2(1169.47,3764.55) cw(c1169.47,3757.29) 1176.73,3757.29
  Layer 8 - Bottom Layer w5: v2(1169.47,3764.55) U12.K8@1182.26,3777.34
CSI1_D2_N: U1.40 U12.G8 | length 665.2
  Layer 1 - Top Layer w5: U1.40@1134.84,3290.73 1134.84,3307.58 ccw(c1126.47,3307.58) 1132.39,3313.5 cw(c1137.22,3318.33) 1130.39,3318.33 1130.39,3386.05 ccw(c1080.79,3386.05) 1115.86,3421.12 1110.55,3426.43 cw(c1130.62,3446.5) 1102.24,3446.5 1102.24,3776.67 cw(c1109.07,3776.67) 1109.07,3783.5 1156.53,3783.5 ccw(c1156.53,3799.71) 1172.74,3799.71 1172.74,3859.03 ccw(c1161.61,3859.03) v2(1169.47,3866.91)
  Layer 8 - Bottom Layer w5: v2(1169.47,3866.91) U12.G8@1182.26,3854.11
CSI1_D2_P: U1.41 U12.G9 | length 671.9
  Layer 1 - Top Layer w5: U1.41@1115.16,3290.73 1115.16,3307.58 cw(c1123.53,3307.58) 1117.61,3313.5 ccw(c1112.78,3318.33) 1119.61,3318.33 1119.61,3386.05 ccw(c1080.79,3386.05) 1108.24,3413.5 1103.41,3418.33 cw(c1131.57,3446.5) 1091.74,3446.5 1091.74,3776.67 cw(c1109.07,3776.67) 1109.07,3794 1156.53,3794 ccw(c1156.53,3799.71) 1162.24,3799.71 1162.24,3842.33 ccw(c1142.51,3842.33) 1156.46,3856.28 1147.21,3865.53 ccw(c1143.88,3862.2) v2(1143.88,3866.91)
  Layer 8 - Bottom Layer w5: v2(1143.88,3866.91) U12.G9@1156.67,3854.11
CSI1_D3_N: U1.42 U12.H9 | length 668.9
  Layer 1 - Top Layer w5: U1.42@1095.47,3290.73 1095.47,3307.58 ccw(c1087.1,3307.58) 1093.02,3313.5 cw(c1097.85,3318.33) 1091.02,3318.33 1091.02,3382.5 ccw(c1054.64,3382.5) 1080.36,3408.23 1077.66,3410.92 cw(c1093.18,3426.44) 1071.24,3426.44 1071.24,3434.22 ccw(c1041.96,3434.22) 1062.66,3454.92 cw(c1080.59,3472.85) 1055.24,3472.85 1055.24,3479.5 cw(c1080.59,3479.5) 1062.66,3497.42 ccw(c1041.96,3518.13) 1071.24,3518.13 1071.24,3524.78 ccw(c1041.96,3524.78) 1062.66,3545.48 cw(c1080.59,3563.41) 1055.24,3563.41 1055.24,3570.06 cw(c1080.59,3570.06) 1062.66,3587.98 ccw(c1041.96,3608.68) 1071.24,3608.68 1071.24,3615.33 ccw(c1041.96,3615.33) 1062.66,3636.04 cw(c1080.59,3653.96) 1055.24,3653.96 1055.24,3660.61 cw(c1080.59,3660.61) 1062.66,3678.54 ccw(c1041.96,3699.24) 1071.24,3699.24 1071.24,3705.89 ccw(c1041.96,3705.89) 1062.66,3726.59 cw(c1080.59,3744.52) 1055.24,3744.52 1055.24,3751.17 cw(c1080.59,3751.17) 1062.66,3769.09 ccw(c1041.96,3789.8) 1071.24,3789.8 1071.24,3807.75 cw(c1077.87,3807.75) 1077.87,3814.39 1119.04,3814.39 ccw(c1119.04,3831.97) 1136.62,3831.97 1136.62,3834.06 cw(c1143.88,3834.06) v2(1143.88,3841.32)
  Layer 8 - Bottom Layer w5: v2(1143.88,3841.32) U12.H9@1156.67,3828.52
CSI1_D3_P: U1.43 U12.H10 | length 668.4
  Layer 1 - Top Layer w5: U1.43@1075.79,3290.73 1075.79,3307.58 cw(c1084.16,3307.58) 1078.24,3313.5 ccw(c1073.41,3318.33) 1080.24,3318.33 1080.24,3382.5 ccw(c1053.68,3382.5) 1072.46,3401.28 1070.24,3403.5 cw(c1093.18,3426.44) 1060.74,3426.44 1060.74,3434.22 ccw(c1041.96,3434.22) 1055.24,3447.5 cw(c1080.59,3472.85) 1044.74,3472.85 1044.74,3479.5 cw(c1080.59,3479.5) 1055.24,3504.85 ccw(c1041.96,3518.13) 1060.74,3518.13 1060.74,3524.78 ccw(c1041.96,3524.78) 1055.24,3538.06 cw(c1080.59,3563.41) 1044.74,3563.41 1044.74,3570.06 cw(c1080.59,3570.06) 1055.24,3595.41 ccw(c1041.96,3608.68) 1060.74,3608.68 1060.74,3615.33 ccw(c1041.96,3615.33) 1055.24,3628.61 cw(c1080.59,3653.96) 1044.74,3653.96 1044.74,3660.61 cw(c1080.59,3660.61) 1055.24,3685.96 ccw(c1041.96,3699.24) 1060.74,3699.24 1060.74,3705.89 ccw(c1041.96,3705.89) 1055.24,3719.17 cw(c1080.59,3744.52) 1044.74,3744.52 1044.74,3751.17 cw(c1080.59,3751.17) 1055.24,3776.52 ccw(c1041.96,3789.8) 1060.74,3789.8 1060.74,3807.75 cw(c1077.87,3807.75) 1077.87,3824.89 1119.04,3824.89 ccw(c1119.04,3831.4) 1125.55,3831.4 1125.55,3834.06 ccw(c1118.29,3834.06) v2(1118.29,3841.32)
  Layer 8 - Bottom Layer w5: v2(1118.29,3841.32) U12.H10@1131.08,3828.52
CTS_SOC: J29.98 U16.24 | length 4852.8
  Layer 1 - Top Layer w8: U16.24@4995.67,1472.05 v1(5080,1472.05)
  Layer 6 - Signal w8: v1(3310.03,3850) 3310.03,3819.97 3325,3805 3500,3805 3918.79,3386.21 5201.21,3386.21 5250,3435 v1(5480,3435)
  Layer 8 - Bottom Layer w8: v1(3310.03,3850) J29.98@3310.03,3900.89 ; v1(5080,1472.05) 5147.05,1472.05 5230,1555 5415,1555 5530,1670 5530,3385 v1(5480,3435)
DVP1_04: R190.2 U8.C4 | length 6140.6
  Layer 3 - Sensitive w5.5: v2(1976.77,3023.82) 1989.5,3011.09 ; 1989.6,3011.09 1989.6,2990.59 1984.4,2985.39 1968.39,2985.39 1963,2980 1963,2892 2054.37,2800.63 2345,2800.63 2370,2775.63 2370,2720 2425,2665 4624,2665 4639,2680 4639,2698 4648,2707 4751,2707 4793,2749 4840,2749 4903,2686 4983,2686 5030,2733 5030,2783.5 5039,2792.5 5071,2792.5 5080,2801.5 5080,2828.5 5071,2837.5 4989,2837.5 4980,2846.5 4980,2873.5 4989,2882.5 5071,2882.5 5080,2891.5 5080,2918.5 5071,2927.5 4989,2927.5 4980,2936.5 4980,2963.5 4989,2972.5 5071,2972.5 5080,2981.5 5080,3008.5 5071,3017.5 4989,3017.5 4980,3026.5 4980,3053.5 4989,3062.5 5071,3062.5 5080,3071.5 5080,3098.5 5071,3107.5 4989,3107.5 4980,3116.5 4980,3143.5 4989,3152.5 5071,3152.5 5080,3161.5 5080,3188.5 5071,3197.5 4989,3197.5 4980,3206.5 4980,3233.5 4989,3242.5 5071,3242.5 5080,3251.5 5080,3278.5 5071,3287.5 4989,3287.5 4980,3296.5 4980,3323.5 4989,3332.5 5071,3332.5 5080,3341.5 5080,3368.5 5071,3377.5 4989,3377.5 4980,3386.5 4980,3413.5 4989,3422.5 5051,3422.5 5060,3431.5 5060,3458.5 5051,3467.5 5039,3467.5 5030,3476.5 5030,3505 4890,3645 4660,3645 4625,3680 ; v1(4571.38,3761.38) 4624.37,3708.39 4624.37,3680
  Layer 8 - Bottom Layer w5: U8.C4@1963.98,3036.61 v2(1976.77,3023.82)
  Layer 8 - Bottom Layer w9.5: R190.2@4535,3761.38 v1(4571.38,3761.38)
DVP1_05: R191.1 U8.B4 | length 6139
  Layer 3 - Sensitive w5.5: v2(2002.36,3023.82) 2015.19,3010.99 2084.74,3010.99 2135.1,2960.63 2379.37,2960.63 2390,2950 3485,2950 3500,2965 3500,2990.75 3493.25,2997.5 3456.75,2997.5 3450,3004.25 3450,3035.75 3456.75,3042.5 3543.25,3042.5 3550,3049.25 3550,3080.75 3543.25,3087.5 3456.75,3087.5 3450,3094.25 3450,3125.75 3456.75,3132.5 3543.25,3132.5 3550,3139.25 3550,3170.75 3543.25,3177.5 3456.75,3177.5 3450,3184.25 3450,3215.75 3456.75,3222.5 3497.5,3222.5 3500,3225 3500,3235 3515,3250 3550.75,3250 3557.5,3256.75 3557.5,3293.25 3564.25,3300 3595.75,3300 3602.5,3293.25 3602.5,3206.75 3609.25,3200 3640.75,3200 3647.5,3206.75 3647.5,3293.25 3654.25,3300 3685.75,3300 3692.5,3293.25 3692.5,3206.75 3699.25,3200 3730.75,3200 3737.5,3206.75 3737.5,3293.25 3744.25,3300 3775.75,3300 3782.5,3293.25 3782.5,3206.75 3789.25,3200 3820.75,3200 3827.5,3206.75 3827.5,3293.25 3834.25,3300 3865.75,3300 3872.5,3293.25 3872.5,3206.75 3879.25,3200 3910.75,3200 3917.5,3206.75 3917.5,3293.25 3924.25,3300 3955.75,3300 3962.5,3293.25 3962.5,3206.75 3969.25,3200 4000.75,3200 4007.5,3206.75 4007.5,3293.25 4014.25,3300 4045.75,3300 4052.5,3293.25 4052.5,3206.75 4059.25,3200 4090.75,3200 4097.5,3206.75 4097.5,3293.25 4104.25,3300 4135.75,3300 4142.5,3293.25 4142.5,3256.75 4149.25,3250 4180,3250 4200,3270 4200,3315.75 4193.25,3322.5 4156.75,3322.5 4150,3329.25 4150,3360.75 4156.75,3367.5 4243.25,3367.5 4250,3374.25 4250,3405.75 4243.25,3412.5 4156.75,3412.5 4150,3419.25 4150,3450.75 4156.75,3457.5 4243.25,3457.5 4250,3464.25 4250,3495.75 4243.25,3502.5 4206.75,3502.5 4200,3509.25 4200,3564 4214,3578 4237,3578 4248,3567 4248,3558 4256,3550 4360,3550 4386.38,3576.38 4386.38,3775 4360,3801.38 4360,3835.75 4353.25,3842.5 4289.37,3842.5 4282.62,3849.25 4282.62,3880.75 4289.37,3887.5 4353.25,3887.5 4360,3894.25 4360,3945.75 4353.25,3952.5 4321.94,3952.5 4315.19,3959.25 4315.19,3990.75 4321.94,3997.5 4353.25,3997.5 4360,4004.25 4360,4362.24 v1(4386.38,4388.62)
  Layer 8 - Bottom Layer w5: U8.B4@1989.57,3036.61 v2(2002.36,3023.82)
  Layer 8 - Bottom Layer w9.5: R191.1@4350,4388.62 v1(4386.38,4388.62)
